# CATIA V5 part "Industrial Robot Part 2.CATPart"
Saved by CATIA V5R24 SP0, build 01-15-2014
Part number: Industrial Robot Part 2
Material "DS Red": density 7860 kg/m3, Young's modulus 2e+11 Pa, Poisson ratio 0.266
Bounding box of the stored display mesh (mm): x -269.69 to 642.341, y -295.632 to 434.368, z -274.844 to 480.347
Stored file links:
  C:\Users\cdl\Downloads\2024_CAD_final\p2\Industrial Robot Part 2.CATPart
  D:\Program Files\Dassault Systemes\B24\win_b64\startup\materials\Catalog.CATMaterial
  D:\Program Files\Dassault Systemes\B24\win_b64\startup\materials\red_env_512x512.jpg
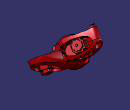
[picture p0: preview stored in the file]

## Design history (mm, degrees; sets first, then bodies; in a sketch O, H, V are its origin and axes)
Body1 (main body), material "DS Red"
  Body2 "Solid 1"
    Solid1: solid without history
  Assemble1: tool Body2
  Body3 "Solid 2"
    Solid2 "Solid.1": solid without history
  Assemble2: tool Body3
  Body4 "Solid 3"
    Solid3 "Solid.1": solid without history
  Assemble3: tool Body4
  Translate1: CoordX 0, CoordY 0, CoordZ 0, ToTransfor Assemble3
  Translate2: Direction (0, 0, 1), Length -401, ToTransfor Translate1
  Rotate1: Axis Z axis, Angle 336, ToTransfor Translate2
  Rotate2: Axis Y axis, Angle 45, ToTransfor Rotate1
  Rotate3: Axis X axis, Angle 333, ToTransfor Rotate2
